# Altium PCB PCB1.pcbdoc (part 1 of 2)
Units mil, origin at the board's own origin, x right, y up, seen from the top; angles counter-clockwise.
Board outline 3937 x 1574.8 mil, 4 copper layers (Top Layer, Inner1, Inner2, Bottom Layer), stack 62.3 mil thick; 79 components, 49 nets, 279 pads, 327 vias.
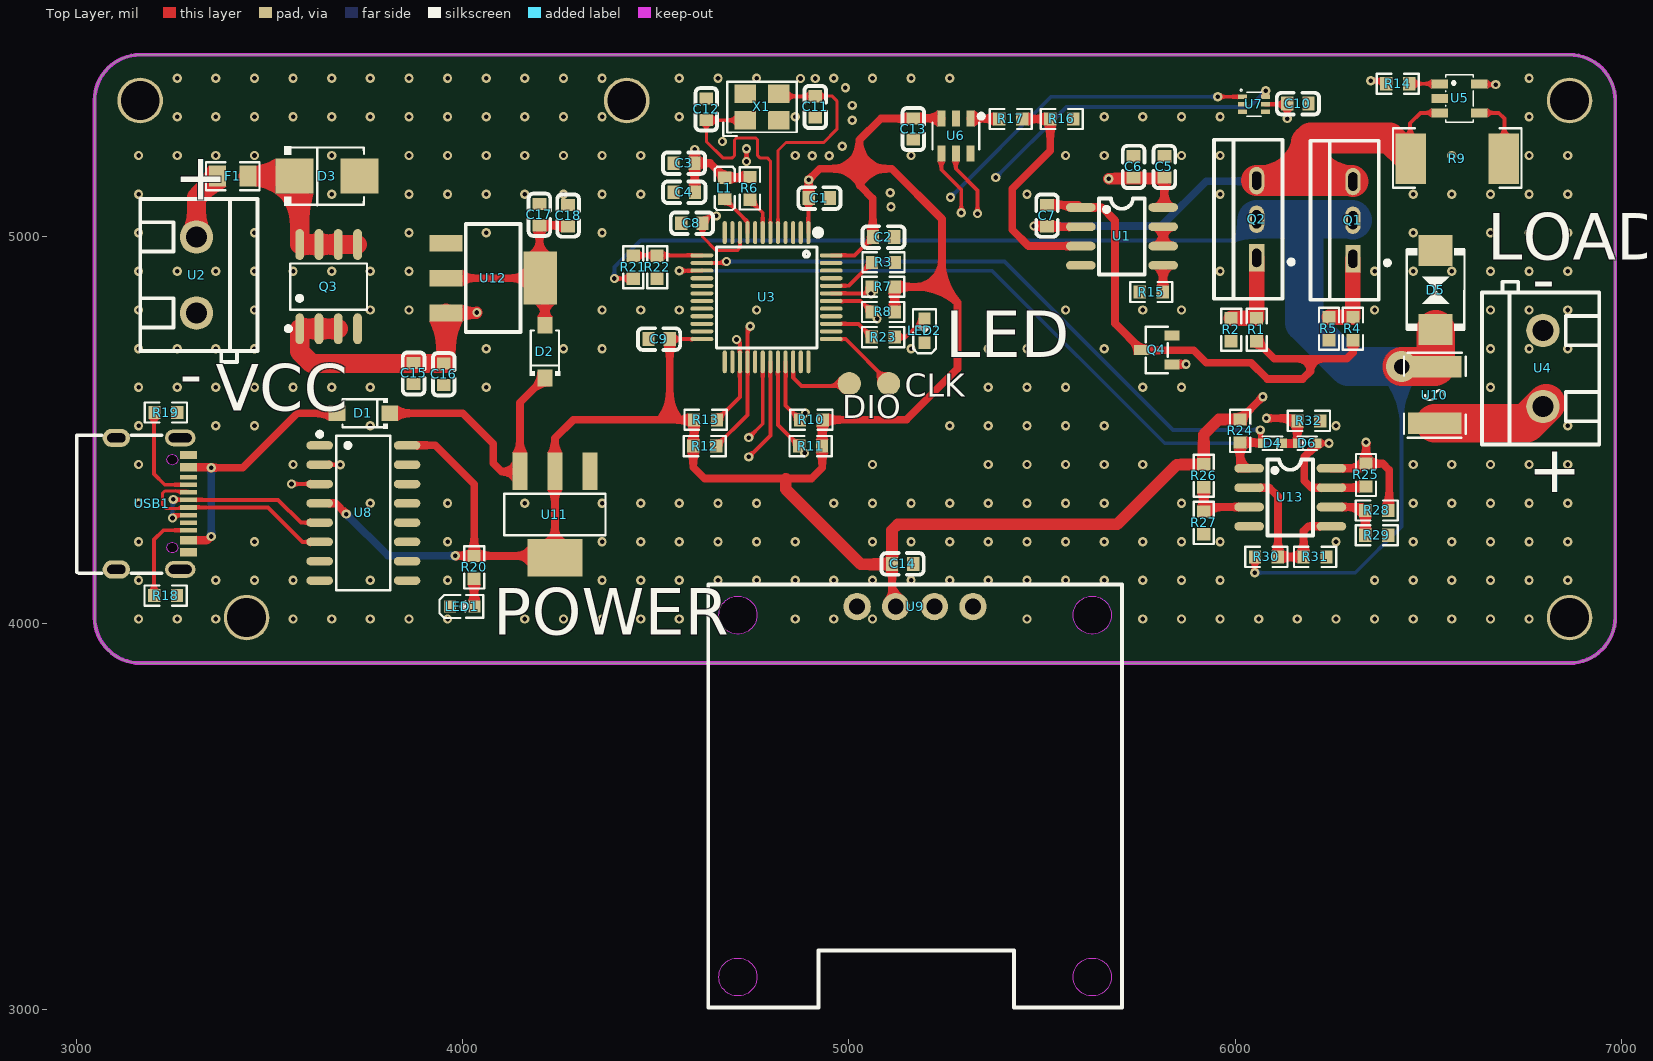
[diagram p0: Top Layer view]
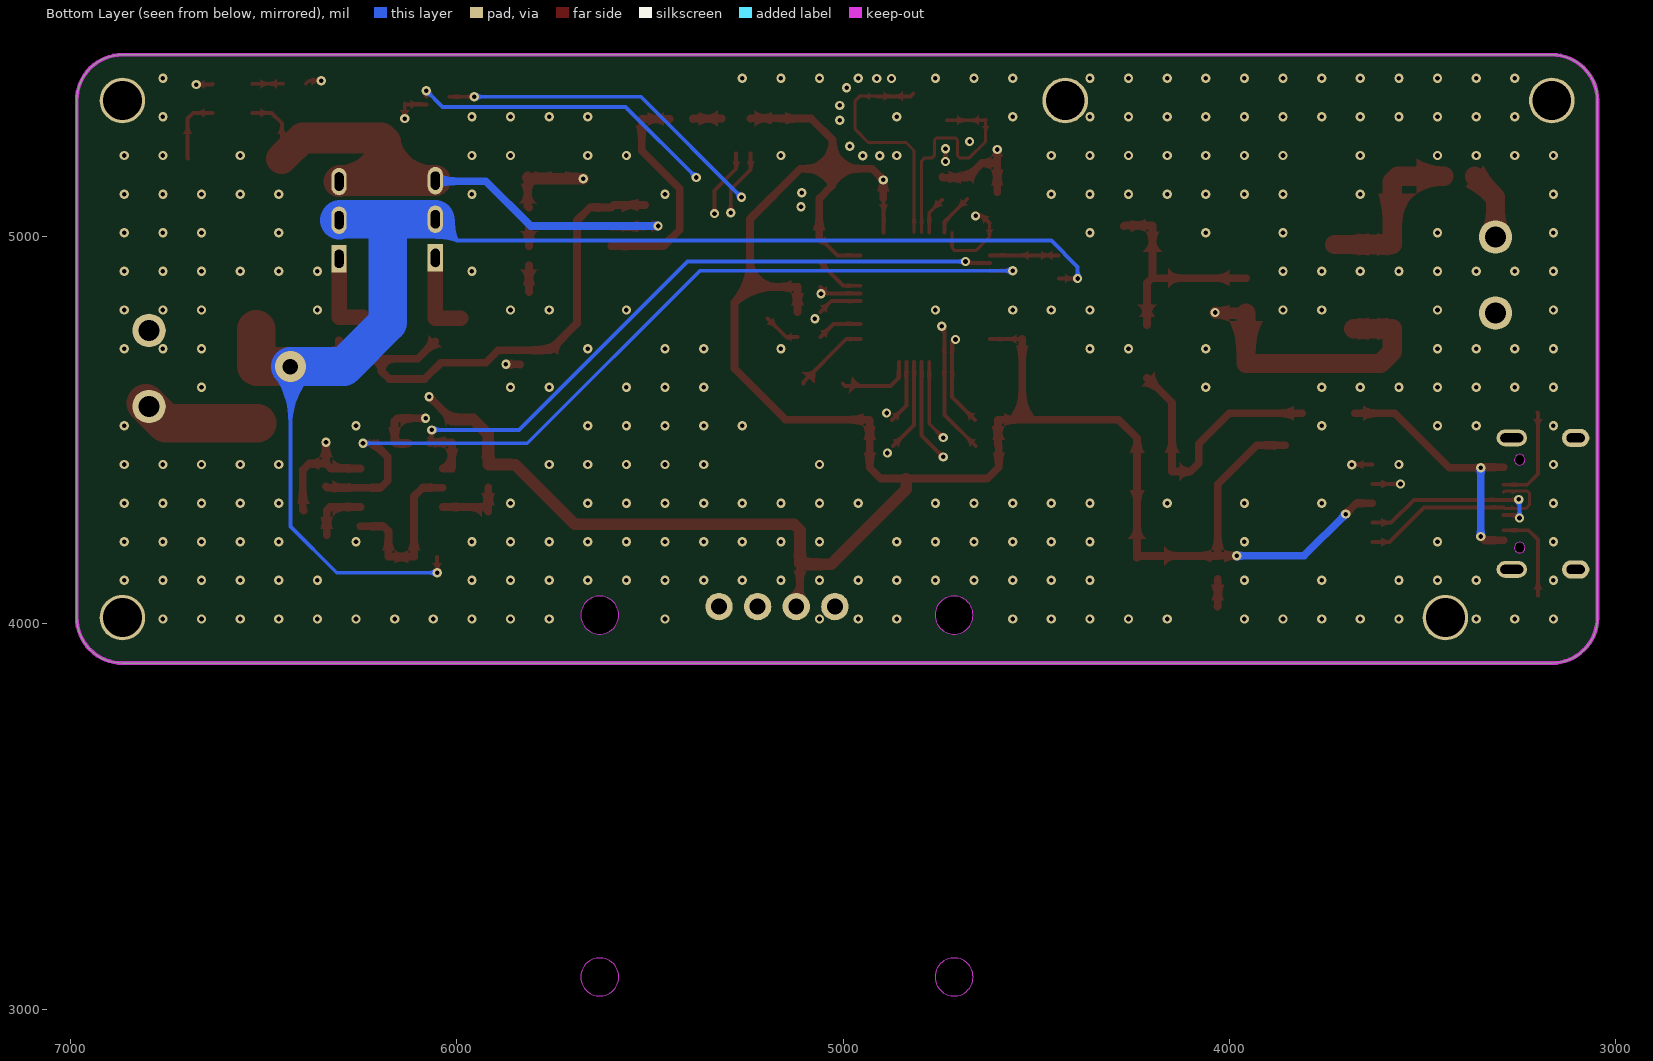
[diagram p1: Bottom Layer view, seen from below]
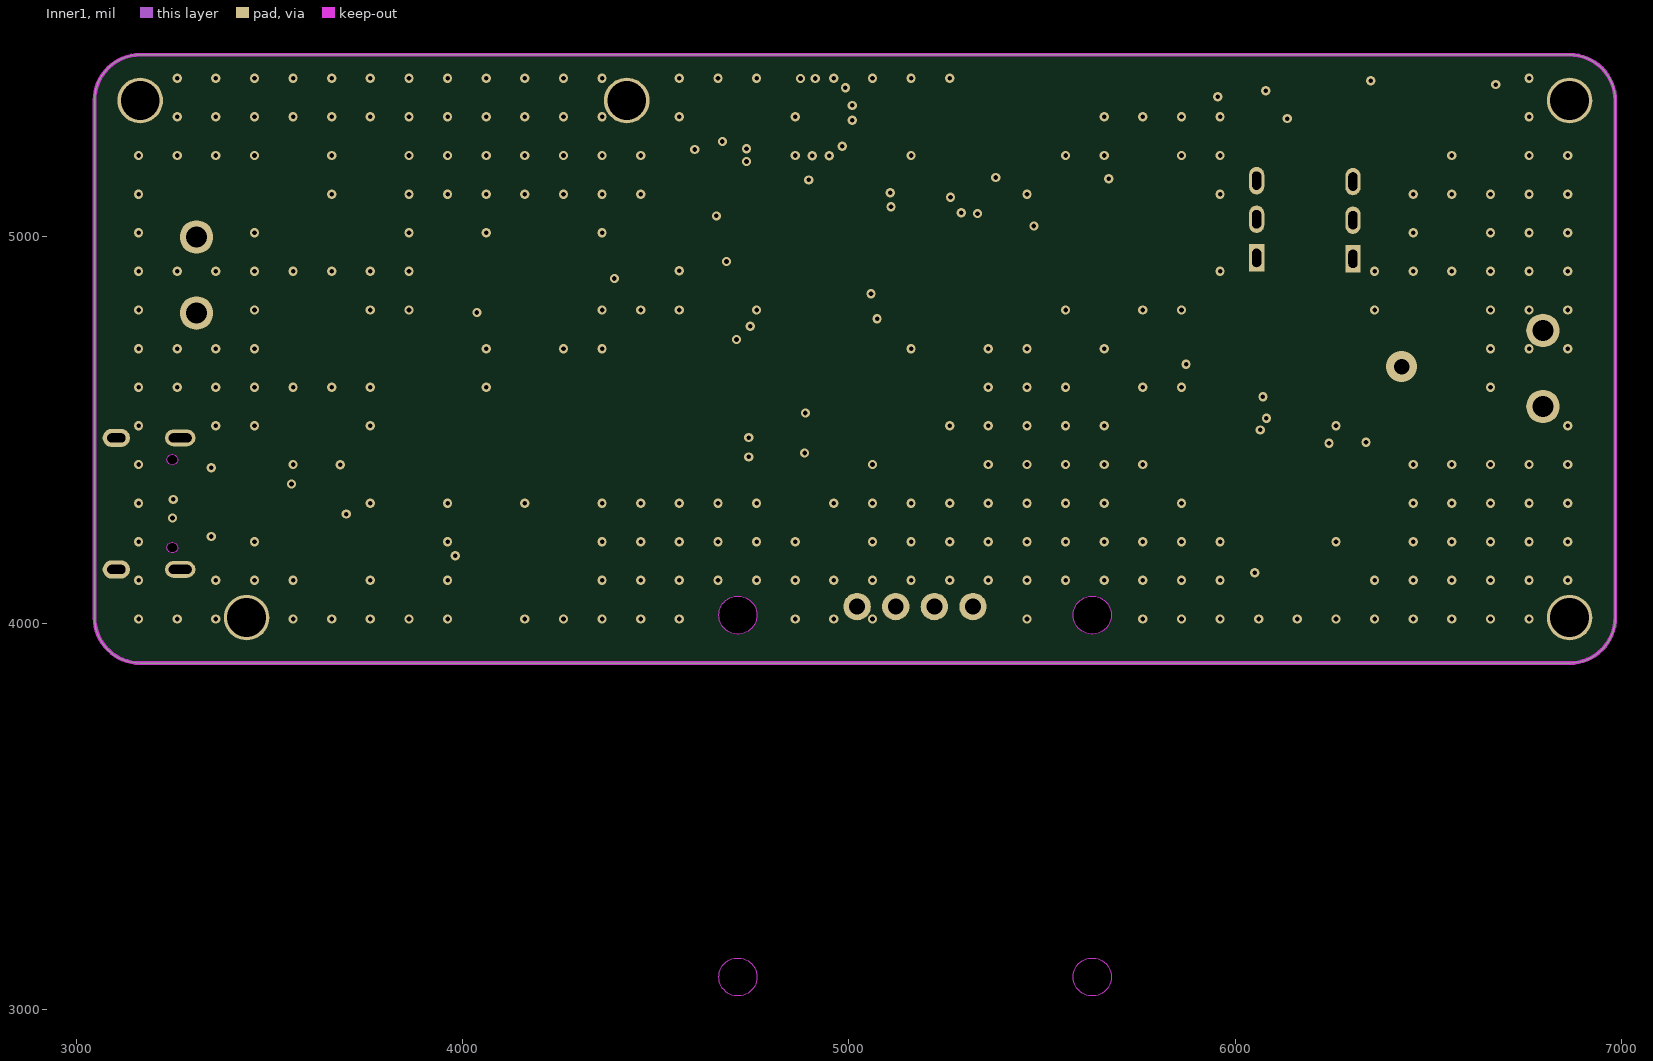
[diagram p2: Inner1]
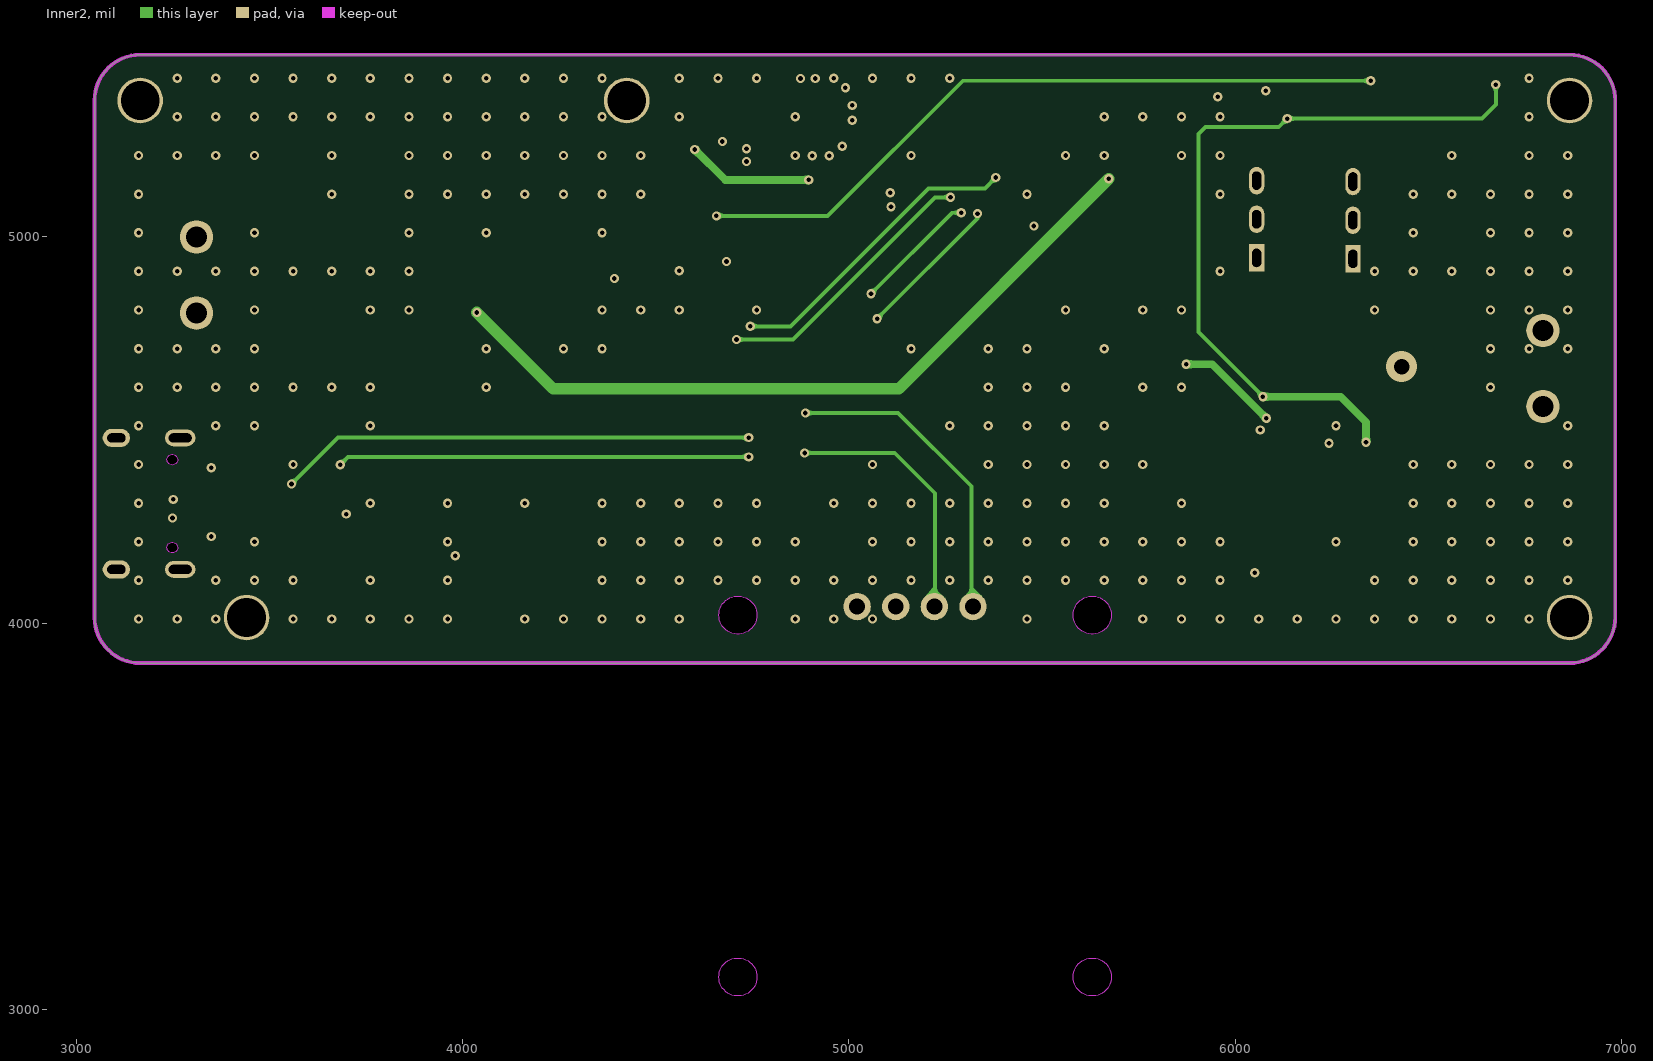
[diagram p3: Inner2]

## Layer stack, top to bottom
Top Solder Mask Layer: solder mask 0.4, Dk 0
Top Layer: signal copper 1.4
Dielectric1: surface 18.9, 7628 RC49% 8.6mil, Dk 0
Inner1: signal copper 1.4
Dielectric2: surface 18.9, 1.1mm H/HOZ Copper, Dk 0
Inner2: signal copper 1.4
Dielectric3: surface 18.9, 7628 RC49% 8.6mil, Dk 0
Bottom Layer: signal copper 1.4
Bottom Solder Mask Layer: solder mask 0.4, Dk 0

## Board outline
3165,5471.3 ccw(c3165,5353.2) 3046.9,5353.2 3046.9,4014.6 ccw(c3165,4014.6) 3165,3896.5 6865.8,3896.5 ccw(c6865.8,4014.6) 6983.9,4014.6 6983.9,5353.2 ccw(c6865.8,5353.2) 6865.8,5471.3

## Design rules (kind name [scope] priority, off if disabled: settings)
BoardOutlineClearance copperThickness1oz [All] p0: genericclearance=10 ignorepadtopadclearanceinfootprint=FALSE except(0: Arc-SplitContinuation Track-SplitContinuation SMDPad-SplitContinuation THPad-SplitContinuation Via-SplitContinuation Fill-SplitContinuation Poly-SplitContinuation Region-SplitContinuation Text-SplitContinuation)
BoardOutlineClearance copperThickness2oz [All] p0: genericclearance=10 ignorepadtopadclearanceinfootprint=FALSE except(0: Arc-SplitContinuation Track-SplitContinuation SMDPad-SplitContinuation THPad-SplitContinuation Via-SplitContinuation Fill-SplitContinuation Poly-SplitContinuation Region-SplitContinuation Text-SplitContinuation)
BoardOutlineClearance otherClearance [All] p0: genericclearance=10 ignorepadtopadclearanceinfootprint=FALSE except(0: Arc-SplitContinuation Track-SplitContinuation SMDPad-SplitContinuation THPad-SplitContinuation Via-SplitContinuation Fill-SplitContinuation Poly-SplitContinuation Region-SplitContinuation Text-SplitContinuation)
Clearance copperThickness1oz [All] p1: gap=7 ignorepadtopadclearanceinfootprint=FALSE
Clearance copperThickness2oz [All] p1: gap=7 ignorepadtopadclearanceinfootprint=FALSE
Clearance otherClearance [All] p1: gap=7 ignorepadtopadclearanceinfootprint=FALSE
DiffPairsRouting differentialPair [All] p1: maxuncoupledlength=10 minlimit=6 maxlimit=Infinity mostfreqgap=6 toplayer_minwidth=5 toplayer_prefwidth=10 toplayer_maxwidth=100 bottomlayer_minwidth=5 bottomlayer_prefwidth=10 bottomlayer_maxwidth=100 midlayer1_minwidth=5 midlayer1_prefwidth=10 midlayer1_maxwidth=100 midlayer2_minwidth=5 midlayer2_prefwidth=10 midlayer2_maxwidth=100
PasteMaskExpansion pasteMaskExpansion [All] p1: expansion=0
PlaneConnect innerPlane [All] p1: planeconnectstyle=Relief reliefexpansion=20 reliefentries=4 reliefconductorwidth=10 reliefairgap=10
PolygonConnect copperRegion [All] p1: connectstyle=Relief reliefentries=4 reliefconductorwidth=10 polygonreliefangle="90 Angle" airgapwidth=10
PolygonConnect copperRegion1 [All] p1: connectstyle=Direct reliefentries=4 reliefconductorwidth=10 polygonreliefangle="90 Angle" airgapwidth=10
RoutingVias viaSize [All] p1: viastyle="Through Hole" holewidth=12.0078 minholewidth=11.811 maxholewidth=248.0314 width=12.0078 minwidth=11.811 maxwidth=248.0314
SolderMaskExpansion solderMaskExpansion [IsVia] p1: useseparateexpansions=TRUE expansion=-1000 expansionbottom=-1000
SolderMaskExpansion solderMaskExpansion [All] p2: useseparateexpansions=TRUE expansion=2 expansionbottom=2
Width copperThickness1oz [All] p1: maxlimit=100 minlimit=5 preferedwidth=10
Width copperThickness2oz [All] p1: maxlimit=100 minlimit=8 preferedwidth=10

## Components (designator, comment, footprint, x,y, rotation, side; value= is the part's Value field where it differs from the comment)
C1 "100nF" C0603#1 4923.6,5100.5 r0 top
C2 "100nF" C0603#1 5089.6,4999.5 r0 top
C3 "100nF" C0603#2 4573.1,5190.9 r0 top
C4 "100nF" C0603#1 4573.6,5115.5 r0 top
C5 "100nF" C0603#2 5816.9,5181.1 r270 top
C6 "100nF" C0603#2 5736.9,5181.1 r270 top
C7 "100nF" C0603#3 5512.9,5055.1 r90 top
C8 "100nF" C0603#1 4593.6,5035.5 r0 top
C9 "100nF" C0603#1 4508.6,4735.5 r180 top
C10 "100nF" C0603#3 6162.6,5345 r180 top
C11 "100nF" C0603#2 4912.9,5336.2 r270 top
C12 "100nF" C0603#2 4630.9,5330.2 r270 top
C13 "100nF" C0603#3 5166.9,5279.1 r90 top
C14 "100nF" C0603#2 5139.1,4153.2 r0 top
C15 "100nF" C0603#3 3872.9,4646.2 r90 top
C16 "100nF" C0603#3 3950.9,4644.2 r90 top
C17 "100nF" C0603#2 4198.9,5057.1 r270 top
C18 "100nF" C0603#2 4272.9,5055.1 r270 top
D1 "B5819W" SOD-123F_L2.7-W1.6-LS3.8-RD-1 3742.9,4543.1 r180 top
D2 "B5819W" SOD-123F_L2.7-W1.6-LS3.8-RD-1 4212.9,4703.1 r90 top
D3 "SMBJ15A" SMB_L4.3-W3.6-LS5.3-RD 3648.9,5157.1 r0 top
D4 "1N4148WT" SOD-523_L1.2-W0.8-LS1.6-FD#1 6096.7,4465.5 r0 top
D5 "SMBJ15CA" SMB_L4.6-W3.6-LS5.4-BI 6518.9,4862.2 r90 top
D6 "1N4148WT" SOD-523_L1.2-W0.8-LS1.6-FD#2 6186.7,4465.5 r180 top
F1 "SMD0805-100-12" R0805 3404.9,5157.1 r0 top
L1 "BLM18PG121SN1D" L0603 4678.6,5125.5 r270 top
LED1 "" LED_0603 4000.9,4043.1 r0 top
LED2 "" LED_0603 5195.6,4759.5 r90 top
Q1 "IRLZ44N(UMW)" TO-220-3_L10.2-W4.5-P2.54-L 6304.9,5043.1 r90 top
Q2 "IRLZ44N(UMW)" TO-220-3_L10.2-W4.5-P2.54-L 6055.6,5045.5 r90 top
Q3 "AO4407A" SOP-8_L5.0-W4.0-P1.27-LS6.0-BL 3652.9,4871.1 r0 top
Q4 "2N7002" SOT-23-3_L2.9-W1.3-P1.90-LS2.4-BR 5796.9,4707.1 r0 top
R1 "10K" R0603#1 6055.6,4759.5 r90 top
R2 "10K" R0603#1 5989.6,4759.5 r270 top
R3 "10K" R0603#2 5089.5,4934 r0 top
R4 "10K" R0603#2 6304.9,4762.2 r90 top
R5 "10K" R0603#3 6242.9,4762.2 r270 top
R6 "10K" R0603#2 4743.6,5125.5 r270 top
R7 "10K" R0603#1 5088.6,4870.5 r0 top
R8 "10K" R0603#1 5088.6,4805.5 r0 top
R9 "50mΩ" RES-SMD_L6.4-W3.2-R2512 6574.9,5202.2 r0 top
R10 "10K" R0603#3 4902.9,4526.2 r0 top
R11 "10K" R0603#3 4900.9,4458.2 r0 top
R12 "10K" R0603#2 4626.9,4458.2 r180 top
R13 "10K" R0603#2 4628.9,4526.2 r180 top
R14 "10K" R0603#3 6420.9,5396.2 r0 top
R15 "10K" R0603#3 5782.9,4857.1 r0 top
R16 "10K" R0603#3 5550.9,5305.1 r0 top
R17 "10K" R0603#3 5418.9,5305.1 r0 top
R18 "10K" R0603#2 3230.9,4071.1 r180 top
R19 "10K" R0603#2 3231.6,4545.1 r180 top
R20 "10K" R0603#3 4029.8,4144.2 r270 top
R21 "10K" R0603#3 4441.6,4921.5 r90 top
R22 "10K" R0603#2 4503.6,4921.5 r270 top
R23 "10K" R0603#1 5088.6,4740.5 r0 top
R24 "10K" R0603#3 6012.7,4497.5 r90 top
R25 "10K" R0603#3 6338.7,4383.5 r90 top
R26 "10K" R0603#2 5918.7,4381.5 r270 top
R27 "10K" R0603#3 5918.7,4259.5 r90 top
R28 "10K" R0603#2 6366.7,4291.5 r0 top
R29 "10K" R0603#2 6366.7,4227.5 r0 top
R30 "10K" R0603#2 6080.7,4171.5 r0 top
R31 "10K" R0603#2 6206.7,4171.5 r0 top
R32 "10K" R0603#3 6190.7,4523.5 r180 top
U1 "LM358DR" SOIC-8_L5.0-W4.0-P1.27-LS6.0-BL 5706.9,5001.1 r270 top
U2 "KF301-5.0-2P" CONN-TH_P5.00_KF301-5.0-2P#1 3310.9,4901.1 r270 top
U3 "AT32F421C8T7" LQFP-48_L7.0-W7.0-P0.50-LS9.0-BL 4786.7,4843.6 r180 top
U4 "KF301-5.0-2P" CONN-TH_P5.00_KF301-5.0-2P#2 6796.9,4659.1 r90 top
U5 "INA180A1IDBVR" SOT-23-5_L3.0-W1.7-P0.95-LS2.8-BR 6580.9,5358.2 r180 top
U6 "MCP4725A0T-E/CH" SOT-23-6_L2.9-W1.6-P0.95-LS2.8-BL 5276.9,5261.1 r180 top
U7 "TMP112AIDRLR" SOT-563_L1.6-W1.2-P0.50-LS1.6-BR 6048.6,5343 r180 top
U8 "CH340C" SOP-16_L10.0-W3.9-P1.27-LS6.0-BL 3742.9,4285.1 r270 top
U9 "HS96L03W2C03" OLED-TH_L27.8-W27.2-P2.54_C9900033791 5171.2,4042.8 r0 top
U10 "BSMD1812-300-24V" F1812 6516.9,4590.2 r90 top
U11 "AMS1117-3.3" SOT-223-4_L6.5-W3.5-P2.30-LS7.0-BR 4238.9,4281.1 r90 top
U12 "AMS1117-5.0" SOT-223_L6.7-W3.5-P2.30-BR 4078.9,4893.1 r180 top
U13 "LM393DR2G" SOIC-8_L5.0-W4.0-P1.27-LS6.0-BL 6142.7,4325.5 r270 top
USB1 "TYPE-C 16PIN 2MD(073)" USB-C-SMD_TYPE-C-16PIN-2MD-073 3196.9,4309.1 r270 top
X1 "8MHz" CRYSTAL-SMD_4P-L3.2-W2.5-BL-1 4774.9,5336.2 r0 top

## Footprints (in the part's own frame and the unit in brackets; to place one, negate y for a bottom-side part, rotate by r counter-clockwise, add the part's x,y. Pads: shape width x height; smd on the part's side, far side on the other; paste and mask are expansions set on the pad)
C0603#1 [mil]
  rect 31.5x35.4 smd: 1(-27.6,0) 2(27.6,0)
  silkscreen extent -55,-28 55,28
C0603#2 [mil]
  rect 31.5x35.4 smd: 1(-27.6,0) 2(27.5,0)
  silkscreen extent -55,-28 55,28
C0603#3 [mil]
  rect 31.5x35.4 smd: 1(-27.5,0) 2(27.6,0)
  silkscreen extent -55,-28 55,28
CONN-TH_P5.00_KF301-5.0-2P#1 [mil]
  round 86.6 hole 55.1 paste+0 mask+2: 1(-98.5,0) 2(98.4,0)
  silkscreen extent -197,-146 225,158
CONN-TH_P5.00_KF301-5.0-2P#2 [mil]
  round 86.6 hole 55.1 paste+0 mask+2: 1(-98.4,0) 2(98.5,0)
  silkscreen extent -197,-146 225,158
CRYSTAL-SMD_4P-L3.2-W2.5-BL-1 [mil]
  rect 55.1x47.2 smd: 1(-43.3,-34.4) 2(43.3,-34.4) 3(43.3,34.5) 4(-43.3,34.5)
  silkscreen extent -100,-75 90,65
F1812 [mil]
  rect 55.4x137.8 smd paste-3937 mask+2: 1(-73,0) 2(73,0)
  silkscreen extent -110,-80 110,80
L0603 [mil]
  rect 31.5x34 smd paste-3937 mask+2: 1(-27.5,0) 2(27.6,0)
  silkscreen extent -56,-26 56,26
LED_0603 [mil]
  rect 31.5x31.5 smd paste+0 mask+2: 1(-33.5,-0.4) 2(29.5,-0.2)
  silkscreen extent -61,-30 53,30
LQFP-48_L7.0-W7.0-P0.50-LS9.0-BL [mil]
  oval 10.6x59.1 smd paste+0 mask+2: 1(-108.3,-167.4) 2(-88.6,-167.4) 3(-68.9,-167.4) 4(-49.3,-167.4) 5(-29.6,-167.4) 6(-9.9,-167.4) 7(9.8,-167.4) 8(29.5,-167.4) 9(49.2,-167.4) 10(68.9,-167.4) 11(88.5,-167.4) 12(108.2,-167.4) 25(108.2,167.3) 26(88.5,167.3) 27(68.9,167.3) 28(49.2,167.3) 29(29.5,167.3) 30(9.8,167.3) 31(-9.9,167.3) 32(-29.6,167.3) 33(-49.3,167.3) 34(-68.9,167.3) 35(-88.6,167.3) 36(-108.3,167.3)
  oval 59.1x10.6 smd paste+0 mask+2: 13(167.3,-108.3) 14(167.3,-88.6) 15(167.3,-68.9) 16(167.3,-49.2) 17(167.3,-29.6) 18(167.3,-9.9) 19(167.3,9.8) 20(167.3,29.5) 21(167.3,49.2) 22(167.3,68.9) 23(167.3,88.5) 24(167.3,108.2) 37(-167.4,108.2) 38(-167.4,88.5) 39(-167.4,68.9) 40(-167.4,49.2) 41(-167.4,29.5) 42(-167.4,9.8) 43(-167.4,-9.9) 44(-167.4,-29.6) 45(-167.4,-49.2) 46(-167.4,-68.9) 47(-167.4,-88.6) 48(-167.4,-108.3)
  silkscreen extent -141,-176 130,132
OLED-TH_L27.8-W27.2-P2.54_C9900033791 [mil]
  round 70.9 hole 41.3 paste+0 mask+2: 1(-150,0) 2(-50,0) 3(50,0) 4(150,0)
  Board Outline Layer lines w0.1: -507.9,-959.1 -507.5,-965.2 -506.3,-971.3 -504.4,-977.2 -501.8,-982.8 -498.5,-988 -494.5,-992.7 -490,-997 -485,-1000.6 -479.6,-1003.6 -473.9,-1005.9 -467.9,-1007.4 -461.7,-1008.2 -455.6,-1008.2 -449.4,-1007.4 -443.4,-1005.9 -437.7,-1003.6 -432.3,-1000.6 -427.3,-997 -422.8,-992.7 -418.8,-988 -415.5,-982.8 -412.9,-977.2 -411,-971.3 -409.8,-965.2 -409.4,-959.1 -409.8,-952.9 -411,-946.8 -412.9,-940.9 -415.5,-935.3 -418.8,-930.1 -422.8,-925.4 -427.3,-921.1 -432.3,-917.5 -437.7,-914.5 -443.4,-912.3 -449.4,-910.7 -455.6,-909.9 -461.7,-909.9 -467.9,-910.7 -473.9,-912.3 -479.6,-914.5 -485,-917.5 -490,-921.1 -494.5,-925.4 -498.5,-930.1 -501.8,-935.3 -504.4,-940.9 -506.3,-946.8 -507.5,-952.9 -507.9,-959.1 ; -507.9,-22.1 -507.5,-28.2 -506.3,-34.3 -504.4,-40.2 -501.8,-45.8 -498.5,-51 -494.5,-55.7 -490,-60 -485,-63.6 -479.6,-66.6 -473.9,-68.9 -467.9,-70.4 -461.7,-71.2 -455.6,-71.2 -449.4,-70.4 -443.4,-68.9 -437.7,-66.6 -432.3,-63.6 -427.3,-60 -422.8,-55.7 -418.8,-51 -415.5,-45.8 -412.9,-40.2 -411,-34.3 -409.8,-28.2 -409.4,-22.1 -409.8,-15.9 -411,-9.8 -412.9,-3.9 -415.5,1.7 -418.8,6.9 -422.8,11.6 -427.3,15.9 -432.3,19.5 -437.7,22.5 -443.4,24.7 -449.4,26.3 -455.6,27.1 -461.7,27.1 -467.9,26.3 -473.9,24.7 -479.6,22.5 -485,19.5 -490,15.9 -494.5,11.6 -498.5,6.9 -501.8,1.7 -504.4,-3.9 -506.3,-9.8 -507.5,-15.9 -507.9,-22.1 ; 409.5,-959.1 409.8,-965.2 411,-971.3 412.9,-977.2 415.5,-982.8 418.9,-988 422.8,-992.7 427.3,-997 432.3,-1000.6 437.7,-1003.6 443.5,-1005.9 449.5,-1007.4 455.6,-1008.2 461.8,-1008.2 467.9,-1007.4 473.9,-1005.9 479.6,-1003.6 485,-1000.6 490,-997 494.5,-992.7 498.5,-988 501.8,-982.8 504.4,-977.2 506.3,-971.3 507.5,-965.2 507.9,-959.1 507.5,-952.9 506.3,-946.8 504.4,-940.9 501.8,-935.3 498.5,-930.1 494.5,-925.4 490,-921.1 485,-917.5 479.6,-914.5 473.9,-912.3 467.9,-910.7 461.8,-909.9 455.6,-909.9 449.5,-910.7 443.5,-912.3 437.7,-914.5 432.3,-917.5 427.3,-921.1 422.8,-925.4 418.9,-930.1 415.5,-935.3 412.9,-940.9 411,-946.8 409.8,-952.9 409.5,-959.1 ; 409.5,-22.1 409.8,-28.2 411,-34.3 412.9,-40.2 415.5,-45.8 418.9,-51 422.8,-55.7 427.3,-60 432.3,-63.6 437.7,-66.6 443.5,-68.9 449.5,-70.4 455.6,-71.2 461.8,-71.2 467.9,-70.4 473.9,-68.9 479.6,-66.6 485,-63.6 490,-60 494.5,-55.7 498.5,-51 501.8,-45.8 504.4,-40.2 506.3,-34.3 507.5,-28.2 507.9,-22.1 507.5,-15.9 506.3,-9.8 504.4,-3.9 501.8,1.7 498.5,6.9 494.5,11.6 490,15.9 485,19.5 479.6,22.5 473.9,24.7 467.9,26.3 461.8,27.1 455.6,27.1 449.5,26.3 443.5,24.7 437.7,22.5 432.3,19.5 427.3,15.9 422.8,11.6 418.9,6.9 415.5,1.7 412.9,-3.9 411,-9.8 409.8,-15.9 409.5,-22.1
  Board Outline Layer region: -409.4,-22.1 -409.8,-28.2 -411,-34.3 -412.9,-40.2 -415.5,-45.8 -418.8,-51 -422.8,-55.7 -427.3,-60 -432.3,-63.6 -437.7,-66.6 -443.4,-68.9 -449.4,-70.4 -455.6,-71.2 -461.7,-71.2 -467.9,-70.4 -473.9,-68.9 -479.6,-66.6 -485,-63.6 -490,-60 -494.5,-55.7 -498.5,-51 -501.8,-45.8 -504.4,-40.2 -506.3,-34.3 -507.5,-28.2 -507.9,-22.1 -507.5,-15.9 -506.3,-9.8 -504.4,-3.9 -501.8,1.7 -498.5,6.9 -494.5,11.6 -490,15.9 -485,19.5 -479.6,22.5 -473.9,24.7 -467.9,26.3 -461.7,27.1 -455.6,27.1 -449.4,26.3 -443.4,24.7 -437.7,22.5 -432.3,19.5 -427.3,15.9 -422.8,11.6 -418.8,6.9 -415.5,1.7 -412.9,-3.9 -411,-9.8 -409.8,-15.9
  Board Outline Layer region: -409.4,-22.1 -409.8,-28.2 -411,-34.3 -412.9,-40.2 -415.5,-45.8 -418.8,-51 -422.8,-55.7 -427.3,-60 -432.3,-63.6 -437.7,-66.6 -443.4,-68.9 -449.4,-70.4 -455.6,-71.2 -461.7,-71.2 -467.9,-70.4 -473.9,-68.9 -479.6,-66.6 -485,-63.6 -490,-60 -494.5,-55.7 -498.5,-51 -501.8,-45.8 -504.4,-40.2 -506.3,-34.3 -507.5,-28.2 -507.9,-22.1 -507.5,-15.9 -506.3,-9.8 -504.4,-3.9 -501.8,1.7 -498.5,6.9 -494.5,11.6 -490,15.9 -485,19.5 -479.6,22.5 -473.9,24.7 -467.9,26.3 -461.7,27.1 -455.6,27.1 -449.4,26.3 -443.4,24.7 -437.7,22.5 -432.3,19.5 -427.3,15.9 -422.8,11.6 -418.8,6.9 -415.5,1.7 -412.9,-3.9 -411,-9.8 -409.8,-15.9
  Board Outline Layer region: 507.9,-22.1 507.5,-28.2 506.3,-34.3 504.4,-40.2 501.8,-45.8 498.5,-51 494.5,-55.7 490,-60 485,-63.6 479.6,-66.6 473.9,-68.9 467.9,-70.4 461.8,-71.2 455.6,-71.2 449.5,-70.4 443.5,-68.9 437.7,-66.6 432.3,-63.6 427.3,-60 422.8,-55.7 418.9,-51 415.5,-45.8 412.9,-40.2 411,-34.3 409.8,-28.2 409.5,-22.1 409.8,-15.9 411,-9.8 412.9,-3.9 415.5,1.7 418.9,6.9 422.8,11.6 427.3,15.9 432.3,19.5 437.7,22.5 443.5,24.7 449.5,26.3 455.6,27.1 461.8,27.1 467.9,26.3 473.9,24.7 479.6,22.5 485,19.5 490,15.9 494.5,11.6 498.5,6.9 501.8,1.7 504.4,-3.9 506.3,-9.8 507.5,-15.9
  Board Outline Layer region: 507.9,-22.1 507.5,-28.2 506.3,-34.3 504.4,-40.2 501.8,-45.8 498.5,-51 494.5,-55.7 490,-60 485,-63.6 479.6,-66.6 473.9,-68.9 467.9,-70.4 461.8,-71.2 455.6,-71.2 449.5,-70.4 443.5,-68.9 437.7,-66.6 432.3,-63.6 427.3,-60 422.8,-55.7 418.9,-51 415.5,-45.8 412.9,-40.2 411,-34.3 409.8,-28.2 409.5,-22.1 409.8,-15.9 411,-9.8 412.9,-3.9 415.5,1.7 418.9,6.9 422.8,11.6 427.3,15.9 432.3,19.5 437.7,22.5 443.5,24.7 449.5,26.3 455.6,27.1 461.8,27.1 467.9,26.3 473.9,24.7 479.6,22.5 485,19.5 490,15.9 494.5,11.6 498.5,6.9 501.8,1.7 504.4,-3.9 506.3,-9.8 507.5,-15.9
  Board Outline Layer region: -409.4,-959.1 -409.8,-965.2 -411,-971.3 -412.9,-977.2 -415.5,-982.8 -418.8,-988 -422.8,-992.7 -427.3,-997 -432.3,-1000.6 -437.7,-1003.6 -443.4,-1005.9 -449.4,-1007.4 -455.6,-1008.2 -461.7,-1008.2 -467.9,-1007.4 -473.9,-1005.9 -479.6,-1003.6 -485,-1000.6 -490,-997 -494.5,-992.7 -498.5,-988 -501.8,-982.8 -504.4,-977.2 -506.3,-971.3 -507.5,-965.2 -507.9,-959.1 -507.5,-952.9 -506.3,-946.8 -504.4,-940.9 -501.8,-935.3 -498.5,-930.1 -494.5,-925.4 -490,-921.1 -485,-917.5 -479.6,-914.5 -473.9,-912.3 -467.9,-910.7 -461.7,-909.9 -455.6,-909.9 -449.4,-910.7 -443.4,-912.3 -437.7,-914.5 -432.3,-917.5 -427.3,-921.1 -422.8,-925.4 -418.8,-930.1 -415.5,-935.3 -412.9,-940.9 -411,-946.8 -409.8,-952.9
  Board Outline Layer region: -409.4,-959.1 -409.8,-965.2 -411,-971.3 -412.9,-977.2 -415.5,-982.8 -418.8,-988 -422.8,-992.7 -427.3,-997 -432.3,-1000.6 -437.7,-1003.6 -443.4,-1005.9 -449.4,-1007.4 -455.6,-1008.2 -461.7,-1008.2 -467.9,-1007.4 -473.9,-1005.9 -479.6,-1003.6 -485,-1000.6 -490,-997 -494.5,-992.7 -498.5,-988 -501.8,-982.8 -504.4,-977.2 -506.3,-971.3 -507.5,-965.2 -507.9,-959.1 -507.5,-952.9 -506.3,-946.8 -504.4,-940.9 -501.8,-935.3 -498.5,-930.1 -494.5,-925.4 -490,-921.1 -485,-917.5 -479.6,-914.5 -473.9,-912.3 -467.9,-910.7 -461.7,-909.9 -455.6,-909.9 -449.4,-910.7 -443.4,-912.3 -437.7,-914.5 -432.3,-917.5 -427.3,-921.1 -422.8,-925.4 -418.8,-930.1 -415.5,-935.3 -412.9,-940.9 -411,-946.8 -409.8,-952.9
  Board Outline Layer region: 507.9,-959.1 507.5,-965.2 506.3,-971.3 504.4,-977.2 501.8,-982.8 498.5,-988 494.5,-992.7 490,-997 485,-1000.6 479.6,-1003.6 473.9,-1005.9 467.9,-1007.4 461.8,-1008.2 455.6,-1008.2 449.5,-1007.4 443.5,-1005.9 437.7,-1003.6 432.3,-1000.6 427.3,-997 422.8,-992.7 418.9,-988 415.5,-982.8 412.9,-977.2 411,-971.3 409.8,-965.2 409.5,-959.1 409.8,-952.9 411,-946.8 412.9,-940.9 415.5,-935.3 418.9,-930.1 422.8,-925.4 427.3,-921.1 432.3,-917.5 437.7,-914.5 443.5,-912.3 449.5,-910.7 455.6,-909.9 461.8,-909.9 467.9,-910.7 473.9,-912.3 479.6,-914.5 485,-917.5 490,-921.1 494.5,-925.4 498.5,-930.1 501.8,-935.3 504.4,-940.9 506.3,-946.8 507.5,-952.9
  Board Outline Layer region: 507.9,-959.1 507.5,-965.2 506.3,-971.3 504.4,-977.2 501.8,-982.8 498.5,-988 494.5,-992.7 490,-997 485,-1000.6 479.6,-1003.6 473.9,-1005.9 467.9,-1007.4 461.8,-1008.2 455.6,-1008.2 449.5,-1007.4 443.5,-1005.9 437.7,-1003.6 432.3,-1000.6 427.3,-997 422.8,-992.7 418.9,-988 415.5,-982.8 412.9,-977.2 411,-971.3 409.8,-965.2 409.5,-959.1 409.8,-952.9 411,-946.8 412.9,-940.9 415.5,-935.3 418.9,-930.1 422.8,-925.4 427.3,-921.1 432.3,-917.5 437.7,-914.5 443.5,-912.3 449.5,-910.7 455.6,-909.9 461.8,-909.9 467.9,-910.7 473.9,-912.3 479.6,-914.5 485,-917.5 490,-921.1 494.5,-925.4 498.5,-930.1 501.8,-935.3 504.4,-940.9 506.3,-946.8 507.5,-952.9
  Multi-Layer board cut-out: -409.4,-22.1 -409.8,-28.2 -411,-34.3 -412.9,-40.2 -415.5,-45.8 -418.8,-51 -422.8,-55.7 -427.3,-60 -432.3,-63.6 -437.7,-66.6 -443.4,-68.9 -449.4,-70.4 -455.6,-71.2 -461.7,-71.2 -467.9,-70.4 -473.9,-68.9 -479.6,-66.6 -485,-63.6 -490,-60 -494.5,-55.7 -498.5,-51 -501.8,-45.8 -504.4,-40.2 -506.3,-34.3 -507.5,-28.2 -507.9,-22.1 -507.5,-15.9 -506.3,-9.8 -504.4,-3.9 -501.8,1.7 -498.5,6.9 -494.5,11.6 -490,15.9 -485,19.5 -479.6,22.5 -473.9,24.7 -467.9,26.3 -461.7,27.1 -455.6,27.1 -449.4,26.3 -443.4,24.7 -437.7,22.5 -432.3,19.5 -427.3,15.9 -422.8,11.6 -418.8,6.9 -415.5,1.7 -412.9,-3.9 -411,-9.8 -409.8,-15.9
  Multi-Layer board cut-out: 507.9,-22.1 507.5,-28.2 506.3,-34.3 504.4,-40.2 501.8,-45.8 498.5,-51 494.5,-55.7 490,-60 485,-63.6 479.6,-66.6 473.9,-68.9 467.9,-70.4 461.8,-71.2 455.6,-71.2 449.5,-70.4 443.5,-68.9 437.7,-66.6 432.3,-63.6 427.3,-60 422.8,-55.7 418.9,-51 415.5,-45.8 412.9,-40.2 411,-34.3 409.8,-28.2 409.5,-22.1 409.8,-15.9 411,-9.8 412.9,-3.9 415.5,1.7 418.9,6.9 422.8,11.6 427.3,15.9 432.3,19.5 437.7,22.5 443.5,24.7 449.5,26.3 455.6,27.1 461.8,27.1 467.9,26.3 473.9,24.7 479.6,22.5 485,19.5 490,15.9 494.5,11.6 498.5,6.9 501.8,1.7 504.4,-3.9 506.3,-9.8 507.5,-15.9
  Multi-Layer board cut-out: -409.4,-959.1 -409.8,-965.2 -411,-971.3 -412.9,-977.2 -415.5,-982.8 -418.8,-988 -422.8,-992.7 -427.3,-997 -432.3,-1000.6 -437.7,-1003.6 -443.4,-1005.9 -449.4,-1007.4 -455.6,-1008.2 -461.7,-1008.2 -467.9,-1007.4 -473.9,-1005.9 -479.6,-1003.6 -485,-1000.6 -490,-997 -494.5,-992.7 -498.5,-988 -501.8,-982.8 -504.4,-977.2 -506.3,-971.3 -507.5,-965.2 -507.9,-959.1 -507.5,-952.9 -506.3,-946.8 -504.4,-940.9 -501.8,-935.3 -498.5,-930.1 -494.5,-925.4 -490,-921.1 -485,-917.5 -479.6,-914.5 -473.9,-912.3 -467.9,-910.7 -461.7,-909.9 -455.6,-909.9 -449.4,-910.7 -443.4,-912.3 -437.7,-914.5 -432.3,-917.5 -427.3,-921.1 -422.8,-925.4 -418.8,-930.1 -415.5,-935.3 -412.9,-940.9 -411,-946.8 -409.8,-952.9
  Multi-Layer board cut-out: 507.9,-959.1 507.5,-965.2 506.3,-971.3 504.4,-977.2 501.8,-982.8 498.5,-988 494.5,-992.7 490,-997 485,-1000.6 479.6,-1003.6 473.9,-1005.9 467.9,-1007.4 461.8,-1008.2 455.6,-1008.2 449.5,-1007.4 443.5,-1005.9 437.7,-1003.6 432.3,-1000.6 427.3,-997 422.8,-992.7 418.9,-988 415.5,-982.8 412.9,-977.2 411,-971.3 409.8,-965.2 409.5,-959.1 409.8,-952.9 411,-946.8 412.9,-940.9 415.5,-935.3 418.9,-930.1 422.8,-925.4 427.3,-921.1 432.3,-917.5 437.7,-914.5 443.5,-912.3 449.5,-910.7 455.6,-909.9 461.8,-909.9 467.9,-910.7 473.9,-912.3 479.6,-914.5 485,-917.5 490,-921.1 494.5,-925.4 498.5,-930.1 501.8,-935.3 504.4,-940.9 506.3,-946.8 507.5,-952.9
  silkscreen extent -535,-1038 535,57
R0603#1 [mil]
  rect 31.8x34 smd paste-3937 mask+2: 1(-29.7,0) 2(29.7,0)
  silkscreen extent -54,-26 54,26
R0603#2 [mil]
  rect 31.8x34 smd paste-3937 mask+2: 1(-29.6,0) 2(29.7,0)
  silkscreen extent -54,-26 55,26
R0603#3 [mil]
  rect 31.8x34 smd paste-3937 mask+2: 1(-29.7,0) 2(29.6,0)
  silkscreen extent -55,-26 55,26
R0805 [mil]
  rect 44.6x54.2 smd paste-3937 mask+2: 1(-39.4,0) 2(39.4,0)
  silkscreen extent -69,-36 69,36
RES-SMD_L6.4-W3.2-R2512 [mil]
  rect 78.7x129.9 smd: 1(-120.7,0) 2(120.7,0)
  silkscreen extent -166,-75 166,79
SMB_L4.3-W3.6-LS5.3-RD [mil]
  rect 98.4x90.6 smd: 1(-84.7,0) 2(84.6,0)
  silkscreen extent -111,-77 96,77
SMB_L4.6-W3.6-LS5.4-BI [mil]
  rect 80.6x88.2 smd: 1(-102,0) 2(102,0)
  silkscreen extent -105,-75 108,75
SOD-123F_L2.7-W1.6-LS3.8-RD-1 [mil]
  rect 43.3x39.4 smd: 1(-68.3,0) 2(68.3,0)
  silkscreen extent -63,-40 54,39
SOD-523_L1.2-W0.8-LS1.6-FD#1 [mil]
  rect 19.7x23.6 smd: 1(-27.5,0) 2(27.6,0)
  silkscreen extent -26,-18 26,18
SOD-523_L1.2-W0.8-LS1.6-FD#2 [mil]
  rect 19.7x23.6 smd: 1(-27.6,0) 2(27.5,0)
  silkscreen extent -26,-18 26,18
SOIC-8_L5.0-W4.0-P1.27-LS6.0-BL [mil]
  oval 22.4x76.8 smd: 1(-75,-106.5) 2(-25,-106.5) 3(25,-106.5) 4(75,-106.5) 5(75,106.5) 6(25,106.5) 7(-25,106.5) 8(-75,106.5)
  silkscreen extent -99,-59 98,59
SOP-8_L5.0-W4.0-P1.27-LS6.0-BL [mil]
  oval 22.6x80.1 smd: 1(-75,-108.9) 2(-25,-108.9) 3(25,-108.9) 4(75,-108.9) 5(75,109) 6(25,109) 7(-25,109) 8(-75,109)
  silkscreen extent -110,-115 99,60
SOP-16_L10.0-W3.9-P1.27-LS6.0-BL [mil]
  oval 22x68.7 smd: 1(-175,-113.1) 2(-125,-113.1) 3(-75,-113.1) 4(-25,-113.1) 5(25,-113.1) 6(75,-113.1) 7(125,-113.1) 8(175,-113.1) 9(175,113.1) 10(125,113.1) 11(75,113.1) 12(25,113.1) 13(-25,113.1) 14(-75,113.1) 15(-125,113.1) 16(-175,113.1)
  silkscreen extent -210,-119 200,70
SOT-23-3_L2.9-W1.3-P1.90-LS2.4-BR [mil]
  rect 39.4x25.6 smd: 1(39.4,-37.4) 2(39.4,37.4) 3(-39.4,0)
  silkscreen extent -29,-60 29,60
SOT-23-5_L3.0-W1.7-P0.95-LS2.8-BR [mil]
  rect 43.3x23.6 smd: 1(51.2,-37.4) 2(51.2,0) 3(51.2,37.4) 4(-51.2,37.4) 5(-51.2,-37.4)
  silkscreen extent -35,-61 35,61
SOT-23-6_L2.9-W1.6-P0.95-LS2.8-BL [mil]
  rect 20.9x42.2 smd: 1(-37.4,-45.3) 2(0,-45.3) 3(37.4,-45.3) 4(37.4,45.2) 5(0,45.2) 6(-37.4,45.2)
  silkscreen extent -72,-57 61,35
SOT-223-4_L6.5-W3.5-P2.30-LS7.0-BR [mil]
  rect 97.2x38.6 smd: 1(111.6,-90.5) 2(111.6,0) 3(111.6,90.6)
  rect 97.2x141.7 smd: 4(-111.6,0)
  silkscreen extent -54,-131 54,131
SOT-223_L6.7-W3.5-P2.30-BR [mil]
  rect 86.6x43.3 smd: 1(122,-90.6) 2(122,0) 3(122,90.5)
  rect 86.6x137.8 smd: 4(-122,0)
  silkscreen extent -71,-140 71,140
SOT-563_L1.6-W1.2-P0.50-LS1.6-BR [mil]
  rect 23.6x11.8 smd: 1(29.6,-19.7) 2(29.6,0) 3(29.6,19.7) 4(-29.5,19.7) 5(-29.5,0) 6(-29.5,-19.7)
  silkscreen extent -19,-39 36,31
TO-220-3_L10.2-W4.5-P2.54-L [mil]
  rect 70.9x39.4 hole 23.6 slot 47.2 at 0 deg: 1(-100,0)
  oval 70.9x39.4 hole 23.6 slot 47.2 at 0 deg: 2(0,0) 3(100,0)
  silkscreen extent -206,-95 206,110
USB-C-SMD_TYPE-C-16PIN-2MD-073 [mil]
  oval 43.3x78.7 hole 23.6 slot 59.1 at 90 deg paste+0 mask+2: 13(-170.3,71.8) 14(170.2,71.8)
  oval 47.2x70.9 hole 23.6 slot 47.2 at 90 deg paste+0 mask+2: 13(-170.3,-93.5) 14(170.2,-93.5)
  rect 21.7x43.3 smd paste-3937 mask+2: A1B12(-126,93.5) A4B9(-94.5,93.5) B1A12(126,93.5) B4A9(94.5,93.5)
  rect 11.8x43.3 smd paste-3937 mask+2: A5(-49.2,93.5) A6(-9.9,93.5) A7(9.8,93.5) A8(49.2,93.5) B5(68.9,93.5) B6(29.5,93.5) B7(-29.6,93.5) B8(-68.9,93.5)
  Board Outline Layer lines w0.1: 113,37.6 116.1,37.8 119.2,38.7 122,40.3 124.3,42.5 126.1,45.2 127.2,48.2 127.5,51.4 127.2,54.5 126.1,57.5 124.3,60.2 122,62.4 119.2,64 116.1,64.9 113,65.1 109.8,64.6 106.9,63.3 104.3,61.4 102.2,58.9 100.8,56.1 100.1,53 100.1,49.8 100.8,46.6 102.2,43.8 104.3,41.3 106.9,39.4 109.8,38.2 113,37.6 ; -114.6,37.6 -111.4,37.8 -108.3,38.7 -105.6,40.3 -103.3,42.5 -101.5,45.2 -100.4,48.2 -100,51.4 -100.4,54.5 -101.5,57.5 -103.3,60.2 -105.6,62.4 -108.3,64 -111.4,64.9 -114.6,65.1 -117.8,64.6 -120.7,63.3 -123.3,61.4 -125.3,58.9 -126.8,56.1 -127.5,53 -127.5,49.8 -126.8,46.6 -125.3,43.8 -123.3,41.3 -120.7,39.4 -117.8,38.2 -114.6,37.6
  Board Outline Layer region: -100,51.4 -100.4,48.2 -101.5,45.2 -103.3,42.5 -105.6,40.3 -108.3,38.7 -111.4,37.8 -114.6,37.6 -117.8,38.2 -120.7,39.4 -123.3,41.3 -125.3,43.8 -126.8,46.6 -127.5,49.8 -127.5,53 -126.8,56.1 -125.3,58.9 -123.3,61.4 -120.7,63.3 -117.8,64.6 -114.6,65.1 -111.4,64.9 -108.3,64 -105.6,62.4 -103.3,60.2 -101.5,57.5 -100.4,54.5
  Board Outline Layer region: -100,51.4 -100.4,48.2 -101.5,45.2 -103.3,42.5 -105.6,40.3 -108.3,38.7 -111.4,37.8 -114.6,37.6 -117.8,38.2 -120.7,39.4 -123.3,41.3 -125.3,43.8 -126.8,46.6 -127.5,49.8 -127.5,53 -126.8,56.1 -125.3,58.9 -123.3,61.4 -120.7,63.3 -117.8,64.6 -114.6,65.1 -111.4,64.9 -108.3,64 -105.6,62.4 -103.3,60.2 -101.5,57.5 -100.4,54.5
  Board Outline Layer region: 127.5,51.4 127.2,48.2 126.1,45.2 124.3,42.5 122,40.3 119.2,38.7 116.1,37.8 113,37.6 109.8,38.2 106.9,39.4 104.3,41.3 102.2,43.8 100.8,46.6 100.1,49.8 100.1,53 100.8,56.1 102.2,58.9 104.3,61.4 106.9,63.3 109.8,64.6 113,65.1 116.1,64.9 119.2,64 122,62.4 124.3,60.2 126.1,57.5 127.2,54.5
  Board Outline Layer region: 127.5,51.4 127.2,48.2 126.1,45.2 124.3,42.5 122,40.3 119.2,38.7 116.1,37.8 113,37.6 109.8,38.2 106.9,39.4 104.3,41.3 102.2,43.8 100.8,46.6 100.1,49.8 100.1,53 100.8,56.1 102.2,58.9 104.3,61.4 106.9,63.3 109.8,64.6 113,65.1 116.1,64.9 119.2,64 122,62.4 124.3,60.2 126.1,57.5 127.2,54.5
  Multi-Layer board cut-out: -100,51.4 -100.4,48.2 -101.5,45.2 -103.3,42.5 -105.6,40.3 -108.3,38.7 -111.4,37.8 -114.6,37.6 -117.8,38.2 -120.7,39.4 -123.3,41.3 -125.3,43.8 -126.8,46.6 -127.5,49.8 -127.5,53 -126.8,56.1 -125.3,58.9 -123.3,61.4 -120.7,63.3 -117.8,64.6 -114.6,65.1 -111.4,64.9 -108.3,64 -105.6,62.4 -103.3,60.2 -101.5,57.5 -100.4,54.5
  Multi-Layer board cut-out: 127.5,51.4 127.2,48.2 126.1,45.2 124.3,42.5 122,40.3 119.2,38.7 116.1,37.8 113,37.6 109.8,38.2 106.9,39.4 104.3,41.3 102.2,43.8 100.8,46.6 100.1,49.8 100.1,53 100.8,56.1 102.2,58.9 104.3,61.4 106.9,63.3 109.8,64.6 113,65.1 116.1,64.9 119.2,64 122,62.4 124.3,60.2 126.1,57.5 127.2,54.5
  silkscreen extent -177,-196 180,24

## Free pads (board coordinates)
  round 118.1 hole 100.4: 1(3165,5352.9) 1(3440.6,4014.3) 1(4424.8,5352.9) 1(6865.8,4014.3) 1(6865.8,5352.9)
  round 60 smd: 1(5000.9,4620.2) 1(5102.9,4620.2)

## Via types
v1: diameter 24, hole 12, Top Layer to Bottom Layer, 326 vias
v2: diameter 80, hole 40, Top Layer to Bottom Layer, 1 vias

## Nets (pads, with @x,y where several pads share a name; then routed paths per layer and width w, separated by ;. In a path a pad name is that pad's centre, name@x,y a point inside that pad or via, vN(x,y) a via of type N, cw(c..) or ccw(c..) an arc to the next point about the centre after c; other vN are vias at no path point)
3V3: C1.1 C2.1 C3.2 C4.2 C9.1 C10.2 C13.2 C14.1 L1.1 R6.1 R7.2 R8.2 R10.2 R11.2 R12.2 R13.2 R20.1 R24.2 R25.2 R26.1 R28.2 U3.1 U3.24 U3.48 U5.5 U6.3 U7.5 U8.4 U8.16 U9.2 U11.2 U11.4 U13.8 | length 9571.6
  Top Layer w10: C9.1@4536.1,4735.5 4536.3,4735.4 U3.24@4619.4,4735.4 ; U3.1@4895,5011 4895,5099.5 C1.1@4896,5100.5 ; U3.48@4954.1,4951.9 5014.5,4951.9 C2.1@5062,4999.5 ; U7.5@6078.1,5343 6133,5343 C10.2@6134.9,5344.9 ; v1(6134.9,5306.2) C10.2@6134.9,5344.9 ; C10.2@6135,5345 C10.2@6134.9,5344.9 ; U5.5@6632.1,5395.6 6633.5,5394.2 v1(6674.9,5394.2)
  Top Layer w20: U8.4@3629.8,4310.1 3671,4310.1 v1(3698.9,4282.2) ; U8.16@3856,4460.1 3856.1,4460.2 3928.9,4460.2 4029.8,4359.3 R20.1@4029.8,4173.9 ; v1(3980.9,4174.2) 4029.5,4174.2 R20.1@4029.8,4173.9 ; C9.1@4536.1,4735.5 4536.1,4527.8 4537.7,4526.2 ; v1(4600.9,5226.2) 4600.6,5226 C3.2@4600.6,5190.9 ; C4.2@4601.1,5115.5 4600.6,5116 C3.2@4600.6,5190.9 ; R6.1@4743.6,5155.1 4741.5,5153 L1.1@4678.6,5153 4640.7,5190.9 C3.2@4600.6,5190.9 ; C1.1@4896,5100.5 v1(4896,5147.4) 4924.9,5176.2 5027.2,5176.2 ; C2.1@5062,4999.5 5062,5099.1 5028.9,5132.2 5028.9,5174.6 5027.2,5176.2 ; C14.1@5111.5,4153.2 5111.5,4052.5 U9.2@5121.2,4042.8 ; R8.2@5118.3,4805.5 R7.2@5118.3,4870.5 5118.5,4870.2 5240.9,4870.2 ; U6.3@5239.5,5306.4 5239.2,5306.7 C13.2@5166.9,5306.7 5166.4,5306.2 5082.9,5306.2 5027.2,5250.6 5027.2,5176.2 ; R24.2@6012.7,4527.1 v1(6071.8,4586.2) ; U13.8@6249.2,4400.5 6326.1,4400.5 R25.2@6338.7,4413.1 ; v1(6338.9,4468.2) 6338.9,4413.3 R25.2@6338.7,4413.1 ; R28.2@6396.4,4291.5 6398.9,4294 6398.9,4396.2 6382,4413.1 R25.2@6338.7,4413.1 ; R20.1@4029.8,4173.9 4234.5,4173.9 U11.4@4238.9,4169.5 U11.2@4238.9,4392.7 4238.9,4478.2 4286.9,4526.2 4537.7,4526.2 ; 4537.7,4526.2 R13.2@4599.2,4526.2 4599.2,4460.2 R12.2@4597.2,4458.2 4597.2,4403.9 4626.9,4374.2 4837,4374.2 4902.9,4374.2 4930.9,4402.2 4930.9,4524.6 R10.2@4932.5,4526.2 5148.9,4526.2 5280.9,4658.2 5280.9,4830.2 5240.9,4870.2 ; 5027.2,5176.2 5110.9,5176.2 5240.9,5046.2 5240.9,4870.2
  Top Layer w30: 4837,4374.2 4836.9,4374.1 4836.9,4346.2 5030.9,4152.2 5110.5,4152.2 C14.1@5111.5,4153.2 5111.5,4240.9 5126.9,4256.2 5694.9,4256.2 5848.9,4410.2 5917.8,4410.2 R26.1@5918.7,4411.1 5918.7,4488.1 5957.8,4527.1 R24.2@6012.7,4527.1
  Inner2 w10: v1(6071.8,4586.2) 5904.9,4753.2 5904.9,5266.2 5922.9,5284.2 6112.9,5284.2 v1(6134.9,5306.2) 6638.9,5306.2 6674.9,5342.2 v1(6674.9,5394.2)
  Inner2 w20: v1(4600.9,5226.2) 4679.7,5147.4 v1(4896,5147.4) ; v1(6071.8,4586.2) 6272.9,4586.2 6338.9,4520.2 v1(6338.9,4468.2)
  Bottom Layer w20: v1(3698.9,4282.2) 3806.9,4174.2 v1(3980.9,4174.2)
